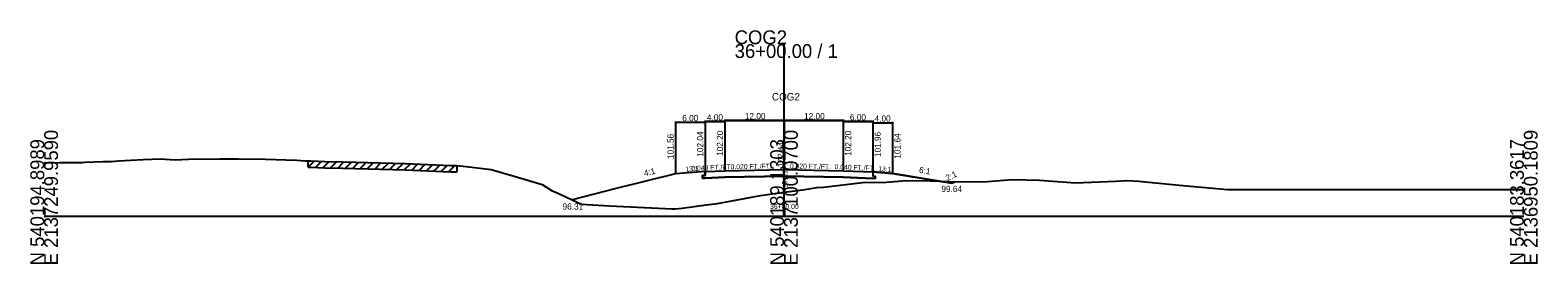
# Model space of a CAD drawing. Extents: x -13397 to 2303, y -10 to 39059.
# Drawn here: x 997.2 to 1302.8, y 11990.3 to 12037.7 of the extents above; entities that cross this region are included whole.
import ezdxf

# ---------------------------------------------------------------- set-up
doc = ezdxf.new("R2010")
doc.units = 0
for name, color, linetype in [('Level 5', 7, 'Continuous'), ('Level 53', 7, 'Continuous'), ('Level 54', 7, 'Continuous'), ('Level 55', 7, 'Continuous'), ('Level 7', 7, 'Continuous'), ('RD_GPK_XS_Cell', 7, 'Continuous'), ('RD_XS_EwShp', 7, 'Continuous'), ('RD_XS_ExGround', 7, 'Continuous'), ('RD_XS_ExPaveRet', 7, 'Continuous'), ('RD_XS_Pave', 7, 'Continuous'), ('RD_XS_TX_Baseline', 7, 'Continuous'), ('RD_XS_TX_Elev_EX', 7, 'Continuous'), ('RD_XS_TX_Elev_PR', 7, 'Continuous'), ('RD_XS_TX_Station', 7, 'Continuous')]:
    doc.layers.add(name, color=color, linetype=linetype)

msp = doc.modelspace()

# ---------------------------------------------------------------- linework, layer by layer
at = {"layer": 'Level 5'}
for p, q in [((1134, 12008.21), (1133.5, 12008.19)), ((1133.5, 12008.19), (1133.5, 12007.69)), ((1133.5, 12007.69), (1134, 12007.71)), ((1134, 12009.04), (1134, 12008.21)), ((1138, 12007.87), (1134, 12007.71)), ((1138, 12007.87), (1134, 12007.71)), ((1138, 12007.87), (1134, 12007.71)), ((1134, 12007.71), (1138, 12007.87)), ((1150, 12008.11), (1138, 12007.87)), ((1150, 12008.11), (1138, 12007.87)), ((1150, 12008.11), (1138, 12007.87)), ((1138, 12007.87), (1150, 12008.11)), ((1138, 12007.87), (1150, 12008.11)), ((1162, 12007.87), (1150, 12008.11)), ((1162, 12007.87), (1150, 12008.11)), ((1150, 12008.11), (1162, 12007.87)), ((1150, 12008.11), (1162, 12007.87)), ((1150, 12008.11), (1162, 12007.87)), ((1168, 12007.63), (1162, 12007.87)), ((1162, 12007.87), (1168, 12007.63)), ((1162, 12007.87), (1168, 12007.63)), ((1162, 12007.87), (1168, 12007.63)), ((1168, 12008.96), (1168, 12008.13)), ((1168, 12008.13), (1168.5, 12008.11)), ((1168.5, 12007.61), (1168, 12007.63)), ((1168.5, 12008.11), (1168.5, 12007.61))]:
    msp.add_line(p, q, dxfattribs=at)
at = {"layer": 'Level 54'}
for p, q in [((1138, 12019.59), (1138, 12009.4)), ((1138, 12019.59), (1138, 12009.4)), ((1138, 12019.59), (1138, 12009.4)), ((1138, 12019.59), (1138, 12009.4)), ((1138, 12019.59), (1138, 12009.4)), ((1150, 12019.59), (1150, 12009.64)), ((1150, 12019.59), (1150, 12009.64)), ((1150, 12019.59), (1150, 12009.64)), ((1150, 12019.59), (1150, 12009.64)), ((1150, 12019.59), (1150, 12009.64)), ((1150, 12019.59), (1150, 12009.64)), ((1150, 12019.59), (1150, 12009.64)), ((1150, 12019.59), (1150, 12009.64)), ((1150, 12019.59), (1150, 12009.64)), ((1150, 12019.59), (1150, 12009.64)), ((1162, 12019.59), (1162, 12009.4)), ((1162, 12019.59), (1162, 12009.4)), ((1162, 12019.59), (1162, 12009.4)), ((1162, 12019.59), (1162, 12009.4)), ((1162, 12019.59), (1162, 12009.4)), ((1128, 12019.19), (1128, 12008.76)), ((1134, 12018.99), (1128, 12018.99)), ((1134, 12019.35), (1134, 12009.24)), ((1134, 12019.35), (1134, 12009.24)), ((1134, 12019.35), (1134, 12009.24)), ((1134, 12019.35), (1134, 12009.24)), ((1134, 12019.19), (1134, 12009.24)), ((1134, 12019.15), (1138, 12019.15)), ((1134, 12019.15), (1138, 12019.15)), ((1134, 12019.15), (1138, 12019.15)), ((1138, 12019.15), (1134, 12019.15)), ((1138, 12019.39), (1150, 12019.39)), ((1138, 12019.39), (1150, 12019.39)), ((1138, 12019.39), (1150, 12019.39)), ((1150, 12019.39), (1138, 12019.39)), ((1150, 12019.39), (1138, 12019.39)), ((1138, 12019.35), (1138, 12009.4)), ((1138, 12019.35), (1138, 12009.4)), ((1138, 12019.35), (1138, 12009.4)), ((1138, 12019.35), (1138, 12009.4)), ((1150, 12019.39), (1162, 12019.39)), ((1150, 12019.39), (1162, 12019.39)), ((1162, 12019.39), (1150, 12019.39)), ((1162, 12019.39), (1150, 12019.39)), ((1162, 12019.39), (1150, 12019.39)), ((1162, 12019.35), (1162, 12009.4)), ((1162, 12019.35), (1162, 12009.4)), ((1162, 12019.35), (1162, 12009.4)), ((1162, 12019.35), (1162, 12009.4)), ((1162, 12019.15), (1168, 12019.15)), ((1168, 12019.15), (1162, 12019.15)), ((1168, 12019.15), (1162, 12019.15)), ((1168, 12019.15), (1162, 12019.15)), ((1168, 12019.35), (1168, 12009.16)), ((1168, 12019.35), (1168, 12009.16)), ((1168, 12019.35), (1168, 12009.16)), ((1168, 12019.35), (1168, 12009.16)), ((1168, 12019.11), (1168, 12009.16)), ((1168, 12018.91), (1172, 12018.91)), ((1172, 12019.11), (1172, 12008.84))]:
    msp.add_line(p, q, dxfattribs=at)
at = {"layer": 'Level 7'}
for p, q in [((1128, 12008.56), (1116, 12005.56)), ((1134, 12009.04), (1128, 12008.56)), ((1168, 12008.96), (1172, 12008.64)), ((1172, 12008.64), (1184, 12006.64)), ((1116, 12005.56), (1107.02, 12003.31)), ((1184, 12006.64), (1184.63, 12006.95))]:
    msp.add_line(p, q, dxfattribs=at)
at = {"layer": 'RD_GPK_XS_Cell'}
for p, q in [((1150, 12000), (1150, 12034.85)), ((1000, 12000), (1150, 12000)), ((1150, 12000), (1300, 12000))]:
    msp.add_line(p, q, dxfattribs=at)
at = {"layer": 'RD_XS_EwShp'}
for points in [[(1179.64, 12007.12), (1181.48, 12007.06), (1172, 12008.64), (1168, 12008.96), (1168, 12008.13), (1168.5, 12008.11), (1168.5, 12007.61), (1168, 12007.63), (1162, 12007.87), (1150, 12008.11), (1138, 12007.87), (1134, 12007.71), (1133.5, 12007.69), (1133.5, 12008.19), (1134, 12008.21), (1134, 12009.04), (1128, 12008.56), (1116, 12005.56), (1107.02, 12003.31), (1108.91, 12002.43), (1114.62, 12002.08), (1125.95, 12001.53), (1127.35, 12001.44), (1127.91, 12001.43), (1129.33, 12001.6), (1134.19, 12002.25), (1136.49, 12002.55), (1145.25, 12004.14), (1150, 12004.81), (1153.28, 12005.27), (1155.08, 12005.5), (1156.63, 12005.76), (1158, 12005.85), (1165.94, 12006.78), (1170.78, 12006.88), (1174.84, 12007.2)], [(1181.48, 12007.06), (1184.63, 12006.95), (1184, 12006.64)]]:
    msp.add_lwpolyline(points, close=True, dxfattribs=at)
at = {"layer": 'RD_XS_ExGround'}
for p, q in [((1000, 12010.81), (1000.53, 12010.82)), ((1000.53, 12010.82), (1003.09, 12010.86)), ((1003.09, 12010.86), (1007.73, 12010.89)), ((1007.73, 12010.89), (1008.28, 12010.95)), ((1008.28, 12010.95), (1011.91, 12011.06)), ((1011.91, 12011.06), (1013.58, 12011.09)), ((1013.58, 12011.09), (1015.06, 12011.2)), ((1015.06, 12011.2), (1020.08, 12011.44)), ((1020.08, 12011.44), (1023.5, 12011.58)), ((1023.5, 12011.58), (1024.52, 12011.51)), ((1024.52, 12011.51), (1026.53, 12011.41)), ((1026.53, 12011.41), (1029.29, 12011.55)), ((1029.29, 12011.55), (1035.59, 12011.62)), ((1035.59, 12011.62), (1039.36, 12011.61)), ((1039.36, 12011.61), (1044.88, 12011.52)), ((1044.88, 12011.52), (1048.99, 12011.38)), ((1048.99, 12011.38), (1051.26, 12011.31)), ((1051.26, 12011.31), (1052.82, 12011.21)), ((1052.82, 12011.21), (1053.52, 12011.2)), ((1053.52, 12011.2), (1054.09, 12011.19)), ((1054.09, 12011.19), (1056.9, 12011.08)), ((1056.9, 12011.08), (1060.53, 12010.99)), ((1060.53, 12010.99), (1073.17, 12010.67)), ((1073.17, 12010.67), (1082.4, 12010.28)), ((1082.4, 12010.28), (1083.64, 12010.24)), ((1083.64, 12010.24), (1085.53, 12010.04)), ((1085.53, 12010.04), (1090.65, 12009.47)), ((1090.65, 12009.47), (1095.29, 12008.08)), ((1095.29, 12008.08), (1100.97, 12006.38)), ((1170.78, 12006.88), (1174.84, 12007.2)), ((1174.84, 12007.2), (1179.64, 12007.12)), ((1191.29, 12007.01), (1196.35, 12007.41)), ((1196.35, 12007.41), (1201.83, 12007.28)), ((1201.83, 12007.28), (1209.13, 12006.73)), ((1217.23, 12007.09), (1219.74, 12007.19)), ((1219.74, 12007.19), (1221.92, 12007.08)), ((1100.97, 12006.38), (1102.98, 12005.14)), ((1102.98, 12005.14), (1103.86, 12004.79)), ((1103.86, 12004.79), (1108.91, 12002.43)), ((1136.49, 12002.55), (1145.25, 12004.14)), ((1145.25, 12004.14), (1150, 12004.81)), ((1150, 12004.81), (1153.28, 12005.27)), ((1153.28, 12005.27), (1155.08, 12005.5)), ((1155.08, 12005.5), (1156.63, 12005.76)), ((1156.63, 12005.76), (1158, 12005.85)), ((1158, 12005.85), (1165.94, 12006.78)), ((1165.94, 12006.78), (1170.78, 12006.88)), ((1179.64, 12007.12), (1185.02, 12006.94)), ((1185.02, 12006.94), (1191.29, 12007.01)), ((1209.13, 12006.73), (1217.23, 12007.09)), ((1221.92, 12007.08), (1229.43, 12006.35)), ((1229.43, 12006.35), (1239.94, 12005.39)), ((1239.94, 12005.39), (1250.95, 12005.39)), ((1250.95, 12005.39), (1266.23, 12005.39)), ((1266.23, 12005.39), (1275.56, 12005.39)), ((1275.56, 12005.39), (1283.3, 12005.39)), ((1283.3, 12005.39), (1287.98, 12005.39)), ((1287.98, 12005.39), (1300, 12005.39)), ((1108.91, 12002.43), (1114.62, 12002.08)), ((1114.62, 12002.08), (1125.95, 12001.53)), ((1125.95, 12001.53), (1127.35, 12001.44)), ((1127.35, 12001.44), (1127.91, 12001.43)), ((1127.91, 12001.43), (1129.33, 12001.6)), ((1129.33, 12001.6), (1134.19, 12002.25)), ((1134.19, 12002.25), (1136.49, 12002.55))]:
    msp.add_line(p, q, dxfattribs=at)
at = {"layer": 'RD_XS_ExPaveRet'}
for p, q in [((1053.52, 12009.9), (1053.52, 12011.2)), ((1053.52, 12009.9), (1054.78, 12011.17)), ((1055.02, 12009.86), (1056.27, 12011.11)), ((1056.52, 12009.8), (1057.78, 12011.06)), ((1058.02, 12009.75), (1059.28, 12011.02)), ((1059.52, 12009.71), (1060.78, 12010.98)), ((1061.02, 12009.67), (1062.29, 12010.94)), ((1062.52, 12009.64), (1063.79, 12010.9)), ((1064.02, 12009.6), (1065.29, 12010.87)), ((1065.52, 12009.56), (1066.79, 12010.83)), ((1067.02, 12009.52), (1068.29, 12010.79)), ((1068.52, 12009.48), (1069.79, 12010.75)), ((1070.02, 12009.45), (1071.29, 12010.71)), ((1071.52, 12009.41), (1072.79, 12010.68)), ((1073.02, 12009.37), (1074.27, 12010.62)), ((1074.52, 12009.31), (1075.77, 12010.56)), ((1076.02, 12009.25), (1077.27, 12010.5)), ((1077.52, 12009.19), (1078.77, 12010.43)), ((1079.02, 12009.12), (1080.27, 12010.37)), ((1080.52, 12009.06), (1081.77, 12010.31)), ((1082.02, 12009), (1083.27, 12010.25)), ((1083.64, 12010.24), (1083.64, 12008.94)), ((1053.52, 12009.9), (1054.09, 12009.89)), ((1054.09, 12009.89), (1056.9, 12009.78)), ((1056.9, 12009.78), (1060.53, 12009.69)), ((1060.53, 12009.69), (1073.17, 12009.37)), ((1073.17, 12009.37), (1082.4, 12008.98)), ((1082.4, 12008.98), (1083.64, 12008.94))]:
    msp.add_line(p, q, dxfattribs=at)
at = {"layer": 'RD_XS_Pave'}
for p, q in [((1134, 12009.04), (1138, 12009.2)), ((1138, 12009.2), (1150, 12009.44)), ((1150, 12009.44), (1162, 12009.2)), ((1162, 12009.2), (1168, 12008.96))]:
    msp.add_line(p, q, dxfattribs=at)

# ---------------------------------------------------------------- texts
at = {"layer": 'Level 53'}
for s, rotation, p in [('101.56', 90, (1127.62, 12011.56)), ('102.04', 90, (1133.62, 12012.04)), ('102.20', 90, (1137.63, 12012.2)), ('102.20', 90, (1137.63, 12012.2)), ('102.20', 90, (1137.63, 12012.2)), ('102.20', 90, (1163.63, 12012.2)), ('102.20', 90, (1163.63, 12012.2)), ('102.20', 90, (1163.63, 12012.2)), ('101.96', 90, (1169.62, 12011.96)), ('101.64', 90, (1173.62, 12011.64)), ('4:1', 14.0362, (1121.76, 12008.03)), ('6:1', 350.5377, (1177.3, 12008.77))]:
    msp.add_text(s, height=1.25, rotation=rotation, dxfattribs=at).set_placement(p)
for s, p in [('99.64', (1181.91, 12004.89)), ('96.31', (1105.11, 12001.31))]:
    msp.add_text(s, height=1.25, dxfattribs=at).set_placement(p)
at = {"layer": 'Level 54'}
for s, p in [('6.00', (1129.37, 12019.24)), ('4.00', (1134.37, 12019.4)), ('4.00', (1134.37, 12019.4)), ('4.00', (1134.37, 12019.4)), ('4.00', (1134.37, 12019.4)), ('12.00', (1142.07, 12019.64)), ('12.00', (1142.07, 12019.64)), ('12.00', (1142.07, 12019.64)), ('12.00', (1142.07, 12019.64)), ('12.00', (1142.07, 12019.64)), ('12.00', (1154.07, 12019.64)), ('12.00', (1154.07, 12019.64)), ('12.00', (1154.07, 12019.64)), ('12.00', (1154.07, 12019.64)), ('12.00', (1154.07, 12019.64)), ('6.00', (1163.37, 12019.4)), ('6.00', (1163.37, 12019.4)), ('6.00', (1163.37, 12019.4)), ('6.00', (1163.37, 12019.4)), ('4.00', (1168.37, 12019.16))]:
    msp.add_text(s, height=1.25, dxfattribs=at).set_placement(p)
at = {"layer": 'Level 55'}
for s, height, rotation, p in [('0.040 FT./FT.', 1, 2.2906, (1131.22, 12009.18)), ('0.040 FT./FT.', 1, 2.2906, (1131.22, 12009.18)), ('0.040 FT./FT.', 1, 2.2906, (1131.22, 12009.18)), ('0.040 FT./FT.', 1, 2.2906, (1131.22, 12009.18)), ('0.020 FT./FT.', 1, 1.1458, (1139.17, 12009.47)), ('0.020 FT./FT.', 1, 1.1458, (1139.17, 12009.47)), ('0.020 FT./FT.', 1, 1.1458, (1139.17, 12009.47)), ('0.020 FT./FT.', 1, 1.1458, (1139.17, 12009.47)), ('0.020 FT./FT.', 1, 1.1458, (1139.17, 12009.47)), ('0.020 FT./FT.', 1, 358.8542, (1151.18, 12009.67)), ('0.020 FT./FT.', 1, 358.8542, (1151.18, 12009.67)), ('0.020 FT./FT.', 1, 358.8542, (1151.18, 12009.67)), ('0.020 FT./FT.', 1, 358.8542, (1151.18, 12009.67)), ('0.020 FT./FT.', 1, 358.8542, (1151.18, 12009.67)), ('0.040 FT./FT.', 1, 357.7094, (1160.24, 12009.52)), ('0.040 FT./FT.', 1, 357.7094, (1160.24, 12009.52)), ('0.040 FT./FT.', 1, 357.7094, (1160.24, 12009.52)), ('0.040 FT./FT.', 1, 357.7094, (1160.24, 12009.52)), ('13:1', 1, 4.5739, (1130.03, 12008.97)), ('13:1', 1, 355.4261, (1169.07, 12009.13)), ('2:1', 1.25, 26.5651, (1183.14, 12007.05))]:
    msp.add_text(s, height=height, rotation=rotation, dxfattribs=at).set_placement(p)
at = {"layer": 'RD_GPK_XS_Cell'}
for s, p in [('36+00.00 / 1', (1140, 12032.05)), ('COG2', (1140, 12034.85))]:
    msp.add_text(s, height=2.8, dxfattribs=at).set_placement(p)
for s, p in [('E 2137249.9590', (1002.8, 11990)), ('E 2137100.0700', (1152.8, 11990)), ('E 2136950.1809', (1302.8, 11990)), ('N 540194.8989', (1000, 11990)), ('N 540189.1303', (1150, 11990)), ('N 540183.3617', (1300, 11990))]:
    msp.add_text(s, height=2.8, rotation=90, dxfattribs=at).set_placement(p)
at = {"layer": 'RD_XS_TX_Baseline'}
msp.add_text('COG2', height=1.5, dxfattribs=at).set_placement((1147.55, 12023.44))
at = {"layer": 'RD_XS_TX_Elev_EX'}
msp.add_text('97.81', height=1, rotation=90, dxfattribs=at).set_placement((1150.75, 12005.81))
at = {"layer": 'RD_XS_TX_Elev_PR'}
msp.add_text(' 102.44', height=1.25, rotation=90, dxfattribs=at).set_placement((1150, 12009.44))
at = {"layer": 'RD_XS_TX_Station'}
msp.add_text('36+00.00', height=1, dxfattribs=at).set_placement((1147.17, 12001.44))

doc.saveas('drawing.dxf')
